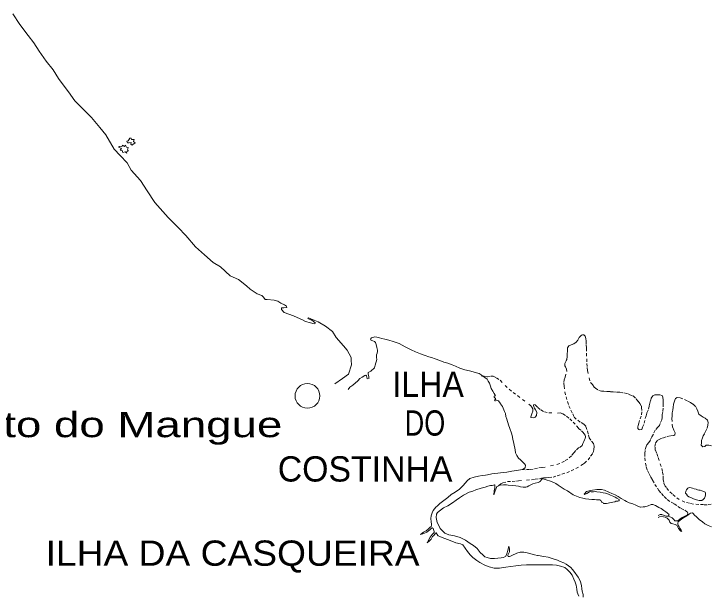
# Model space of a CAD drawing. Extents: x 47169 to 972804, y 7447977 to 9608469.
# Drawn here: x 737887 to 756613, y 9434013 to 9449735 of the extents above; entities that cross this region are included whole.
import ezdxf

# ---------------------------------------------------------------- set-up
doc = ezdxf.new("R2010")
doc.units = 0
doc.header["$LTSCALE"] = 270
doc.linetypes.add('DOTTED', pattern=[1.5, 0.3, -1.2])
doc.layers.add('1', color=7, linetype='Continuous', lineweight=13)
doc.layers.add('2', color=7, linetype='Continuous', lineweight=13)
doc.layers.add('3', color=7, linetype='Continuous')

msp = doc.modelspace()

# ---------------------------------------------------------------- linework, layer by layer
at = {"layer": '1'}
for points in [[(746533.7, 9439762), (746737.2, 9439904), (746899.6, 9440021.8), (746980.3, 9440273.8), (746969.7, 9440401), (746968.8, 9440475.1), (746866.3, 9440668), (746766.9, 9440787.8), (746569.1, 9441015.2), (746472, 9441172.7), (746280.6, 9441317.1), (746079.1, 9441432.9), (745989.3, 9441470.8), (745818.8, 9441541.1), (745805.4, 9441520.1), (745844.1, 9441503.3), (745895.1, 9441485.5), (745936.1, 9441459.9), (746008, 9441394.4), (745979.1, 9441381.2), (745872.6, 9441403.7), (745745.2, 9441441.7), (745661, 9441486.3), (745518.2, 9441552), (745416.2, 9441597.7), (745165.8, 9441680.5), (745094, 9441765.9), (745096.4, 9441806.8), (745155.2, 9441807.7), (745241.7, 9441820.7), (745228.6, 9441858.3), (745172.1, 9441896.1), (745075.7, 9441939.6), (744993.8, 9441987.5), (744901.8, 9442014.3), (744711.1, 9442033.8), (744654.5, 9442034), (744611.5, 9442097.2), (744565, 9442142.7), (744435.4, 9442185.2), (744253.9, 9442311.9), (744151, 9442402.9), (743934.2, 9442577.3), (743717, 9442669.9), (743453.9, 9442918.6), (743254.6, 9443029.9), (743022.3, 9443241.9), (742774.5, 9443457.4), (742518.2, 9443761.3), (742315.9, 9443976.6), (742045, 9444247.4), (741681.4, 9444653.5), (741473.8, 9444967.3), (741299.5, 9445244.4), (741048.6, 9445525.1), (740940.5, 9445717.9), (740745.9, 9445913.3), (740584.5, 9446085.3), (740363.9, 9446471), (740200.4, 9446671.7), (739980.5, 9446945.7), (739527.1, 9447394.1), (739356, 9447636.9), (739214.6, 9447824.3), (739092, 9447995), (738947.5, 9448231.1), (738756.3, 9448456.3), (738568.6, 9448732.4), (738422.8, 9448953), (738273.7, 9449151.5), (738046.2, 9449450.9), (737854.1, 9449734.7)], [(751534.3, 9437441.4), (751588.7, 9437450.1), (751658.7, 9437496.3), (751665.6, 9437570.4), (751644.7, 9437608.1), (751577.2, 9437665.8), (751533, 9437710.2), (751475.5, 9437759.1), (751430.2, 9437827.9), (751396.1, 9437897.7), (751385.3, 9437985.1), (751352.6, 9438151.2), (751328.6, 9438268.5), (751309, 9438368.2), (751290.4, 9438429.1), (751243.1, 9438562), (751206.8, 9438655), (751164.1, 9438813.4), (751137.7, 9438877.6), (751125.8, 9438959.6), (751102.7, 9439013.8), (751048.8, 9439146.8), (750998.1, 9439223.3), (750981.5, 9439242.2), (750939.5, 9439299.8), (750900.7, 9439309.9), (750863, 9439300.1), (750838.6, 9439300.2), (750836.5, 9439331.2), (750856.4, 9439336.6), (750870.9, 9439348.7), (750863.2, 9439368.7), (750841.1, 9439387.6), (750822.3, 9439404.2), (750826.8, 9439427.4), (750856.8, 9439440.6), (750850.2, 9439459.4), (750822.6, 9439502.7), (750786.2, 9439562.6), (750742.1, 9439634.6), (750722.4, 9439697.7), (750699.3, 9439776.4), (750666.3, 9439835.1), (750632.1, 9439887.2), (750572.3, 9439929.5), (750518.1, 9439968.4), (750473.8, 9440000.6), (750415.2, 9440038.4), (750347.6, 9440059.7), (750261.1, 9440082.1), (750160.3, 9440114.5), (750037.2, 9440143.7), (749898.7, 9440185.1), (749783.5, 9440234.2), (749692.7, 9440272.1), (749576.3, 9440317.9), (749472.2, 9440349.2), (749359.2, 9440392.8), (749231.8, 9440436.4), (749134.2, 9440467.7), (749064.4, 9440493.4), (748961.4, 9440529.1), (748837.3, 9440574.9), (748705.5, 9440622.9), (748586.9, 9440677.5), (748495, 9440725.4), (748427.5, 9440757.7), (748345.5, 9440803.4), (748266.9, 9440847.9), (748181.6, 9440880.3), (748100.7, 9440903.8), (747989.9, 9440935.1), (747876.8, 9440967.6), (747795.9, 9440986.7), (747736.1, 9441004.6), (747664, 9441015.9), (747608.6, 9441028.3), (747520.9, 9441003.1), (747490.8, 9440965.6), (747511.8, 9440933.5), (747558.3, 9440921.1), (747596, 9440903.3), (747626.9, 9440875.6), (747648.9, 9440818), (747660.9, 9440743.8), (747678.4, 9440674), (747679.3, 9440633.1), (747670.3, 9440584.5), (747655.7, 9440540.2), (747656.7, 9440503.7), (747655.5, 9440467.2), (747658.7, 9440424.1), (747657.4, 9440382.1), (747640.6, 9440325.7), (747617.1, 9440264.9), (747604.6, 9440195.3), (747503.4, 9440107.1), (747430, 9440069.8), (747429.9, 9440032.2), (747445.1, 9439946.9), (747449.4, 9439897.1)], [(746889.3, 9439611.4), (746938.3, 9439673.2), (747017.3, 9439729.4), (747150.8, 9439842.8), (747204.3, 9439904.6), (747264.3, 9439942), (747343.2, 9439987.1), (747364.3, 9439999.2), (747386.4, 9439978.1), (747406.2, 9439906.1), (747412.8, 9439895.1)], [(748842.2, 9435697.3), (748922.7, 9435762.4), (748990.4, 9435796.4), (749043.9, 9435846), (749091.7, 9435884.6), (749122.9, 9435919.9), (749134.1, 9435950.8), (749135.3, 9435981.8), (749128.8, 9436042.7), (749117, 9436127.9), (749127.2, 9436199.8), (749157.4, 9436288.1), (749177.6, 9436344.5), (749214.4, 9436390.8), (749251.1, 9436433.8), (749296.7, 9436471.3), (749359.1, 9436533), (749433.6, 9436587), (749577.1, 9436700.4), (749669.4, 9436780.9), (749769.5, 9436839.1), (749888.4, 9436920.6), (749984.2, 9437025.3), (750093.3, 9437143.3), (750172.3, 9437208.3), (750285.6, 9437247.8), (750397.8, 9437275), (750503.2, 9437290.2), (750587.5, 9437300.9), (750644.1, 9437308.5), (750762.9, 9437331.3), (750920.5, 9437356.2), (751061.5, 9437374.5), (751168, 9437384.1), (751299, 9437404.6), (751423.3, 9437426.3), (751534.3, 9437441.4)], [(750817.5, 9436769.1), (750826.1, 9436880.3), (750843.7, 9436962.6), (750841.7, 9437026.8), (750828.4, 9437035.7), (750806.2, 9437029.1), (750768.5, 9437024.8), (750726.3, 9437019.4), (750654.2, 9437000.9), (750580.8, 9436972.4), (750474.2, 9436946.2), (750333.2, 9436903.6), (750246.6, 9436869.6), (750154.4, 9436840), (749999.9, 9436764.2), (749893.2, 9436689.4), (749804.2, 9436628.8), (749698.6, 9436555.1), (749571.8, 9436469.2), (749455.2, 9436422.1), (749374, 9436359.3), (749300.6, 9436297.6), (749270.4, 9436245.7), (749264.6, 9436156.1), (749285.2, 9436026.6), (749321.6, 9435956.8), (749367.8, 9435863.7), (749439.7, 9435791.6), (749496.1, 9435738.3), (749603.5, 9435694.7), (749755.4, 9435664.3), (749910.5, 9435621.8), (750048.9, 9435550.5), (750174, 9435458.2), (750262.5, 9435402.6), (750364.3, 9435319.3), (750442.7, 9435212.8), (750515.7, 9435152.8), (750573.2, 9435099.5), (750637.4, 9435078.2), (750727.2, 9435056.9), (750835.9, 9435053.2), (751010.1, 9435069.2), (751075.6, 9435084.5), (751135.6, 9435114.1), (751166.9, 9435179.3), (751192.7, 9435265.5), (751218.1, 9435387.4)], [(754734.5, 9436445.5), (754713.4, 9436451.1), (754639.2, 9436487.9), (754555.1, 9436528), (754464.2, 9436558.2), (754391.1, 9436588.3), (754339, 9436612.8), (754241.6, 9436668.5), (754166.4, 9436720.8), (754085.6, 9436768.6), (753993.6, 9436807.7), (753910.6, 9436845.6), (753797.6, 9436896.9), (753712.2, 9436916), (753589.1, 9436915.3), (753474.8, 9436898), (753386, 9436880.6), (753311.6, 9436859.9), (753252.6, 9436800.3), (753248.1, 9436784.9), (753255.8, 9436781.5), (753319.1, 9436806.8), (753392.5, 9436847.4), (753417, 9436856.2), (753435.8, 9436847.3), (753468, 9436847.2), (753501.2, 9436853.7), (753541.2, 9436863.5), (753591.1, 9436850), (753683.1, 9436838.7), (753757.4, 9436827.3), (753822.8, 9436811.6), (753907, 9436783.7), (753955.7, 9436762.5), (754048.8, 9436726.7), (754086.4, 9436703.4), (754129.6, 9436675.6), (754190.5, 9436639.9), (754190.4, 9436616.7), (754177.1, 9436607.9), (754156, 9436596.9), (754104.9, 9436596), (754078.2, 9436581.7), (754020.5, 9436573), (753978.3, 9436565.5), (753852.9, 9436539.3), (753785.2, 9436539.6), (753767.5, 9436539.7), (753755.3, 9436549.7), (753722.1, 9436568.6), (753711, 9436580.8), (753699, 9436612.9), (753673.5, 9436632.9), (753655.8, 9436633), (753615.8, 9436636.4), (753583.7, 9436637.7), (753527.1, 9436645.6), (753451.7, 9436648.1), (753374.1, 9436656.1), (753286.5, 9436663.1), (753215.5, 9436675.5), (753126.9, 9436701.2), (753041.6, 9436736.9), (752953, 9436773.8), (752802.5, 9436879.4), (752707.2, 9436924), (752630.9, 9436978.5), (752551.2, 9437028.5), (752483.7, 9437077.4), (752387.3, 9437124.2), (752316.4, 9437149.9), (752247.7, 9437162.3), (752198.9, 9437180.2), (752142.4, 9437200.3), (752114.7, 9437200.4), (752100.2, 9437187.2), (752082.4, 9437155.2), (752075.7, 9437140.8), (752042.3, 9437122.1), (752004.6, 9437105.7), (751924.6, 9437082.7), (751869.1, 9437066.3), (751796.8, 9437034.5), (751754.6, 9437012.5), (751713.5, 9436989.4), (751672.4, 9436976.3), (751607, 9436976.5), (751534.9, 9436987.8), (751477.2, 9436999.1), (751404.1, 9437010.4), (751314.3, 9437021.8), (751201.1, 9437032.2), (751155.7, 9437036.7), (751071.4, 9437039.2), (750982.6, 9437030.7), (750940.4, 9437015.4), (750903.7, 9436994.5), (750898.2, 9436990.1), (750885.9, 9436971.3), (750848.9, 9436875.2), (750817.5, 9436769.1)], [(755237.3, 9436208.1), (755258.4, 9436220.2), (755296.2, 9436237.7), (755343.8, 9436235.3), (755399.2, 9436214.1), (755453.5, 9436195.1), (755506.8, 9436191.6), (755541.3, 9436228), (755524.7, 9436248), (755497.1, 9436269.1), (755479.4, 9436286.8), (755444, 9436309.1), (755390.8, 9436349.1), (755323.4, 9436402.5), (755260.2, 9436431.5), (755170.6, 9436486), (755096.3, 9436509.5), (755054.2, 9436509.6), (754969.8, 9436476.8), (754883.1, 9436449.4), (754833.2, 9436442.9), (754767.7, 9436439.8), (754757.8, 9436439.9), (754734.5, 9436445.5)], [(756676.1, 9435904.2), (756589.7, 9435944.3), (756498.9, 9435987.8), (756433.6, 9436042.2), (756347.3, 9436109), (756274.4, 9436175.6), (756215.8, 9436224.5), (756184.8, 9436262.2), (756162.7, 9436283.3), (756115, 9436277.9), (756082.7, 9436253.7), (756012.7, 9436207.5), (755903.7, 9436138.2), (755837, 9436089.8), (755780.2, 9436039.1), (755770.1, 9436007), (755773.3, 9435977.1), (755784.3, 9435938.4), (755803.1, 9435907.3), (755821.8, 9435868.6), (755860.4, 9435816.4), (755880.3, 9435785.4), (755852.6, 9435789.9), (755822.7, 9435813.2), (755809.5, 9435842), (755791.8, 9435866.5), (755752.1, 9435934.1), (755745.5, 9435951.8), (755736.7, 9435955.2), (755700.1, 9435973), (755638.1, 9435987.6), (755593.7, 9435995.5), (755559.5, 9436034.3), (755545.1, 9436060.9), (755534.1, 9436087.5), (755481.1, 9436143), (755425.7, 9436168.7), (755381.4, 9436174.4), (755318.2, 9436190.1), (755272.7, 9436177), (755241.5, 9436159.4)], [(749018.8, 9435476), (749100.8, 9435625.7), (749153.2, 9435703), (749208.8, 9435757), (749206.7, 9435785.7), (749184.8, 9435859.9), (749153.8, 9435883.3), (749137.1, 9435873.4), (749114.9, 9435855.8), (749091.5, 9435828.2), (749057, 9435798.4), (749013.6, 9435766.5), (748929.2, 9435729.2), (748842.2, 9435697.3)], [(753103, 9434037.4), (753078.8, 9434100.5), (753063.5, 9434149.2), (753048.2, 9434229), (753030.8, 9434336.3), (753001.2, 9434411.7), (752973.7, 9434494.7), (752923.1, 9434607.8), (752857.9, 9434687.6), (752788.3, 9434756.5), (752726.4, 9434809.8), (752612.2, 9434847.8), (752499.2, 9434870.3), (752398.3, 9434886.2), (752152, 9434885.9), (752050, 9434886.3), (751881.4, 9434885.8), (751696.1, 9434884.2), (751554.1, 9434878.1), (751407.6, 9434856.5), (751133.5, 9434818.7), (750971.4, 9434791.7), (750820.6, 9434793.3), (750690.9, 9434828), (750569, 9434873.8), (750438.4, 9434945.1), (750357.6, 9435000.7), (750252.5, 9435080.7), (750180.7, 9435149.6), (750108.9, 9435241.6), (749975.3, 9435421.3), (749913.3, 9435451.4), (749791.3, 9435479.5), (749596.4, 9435558.7), (749467.8, 9435600.1), (749363.7, 9435642.5), (749315, 9435662.6), (749313.9, 9435662.6), (749306.2, 9435673.7), (749259.8, 9435742.4), (749246.5, 9435740.2), (749227.5, 9435709.3), (749201.9, 9435677.3), (749164.1, 9435647.6), (749122.8, 9435575.8), (749085, 9435530.5), (749018.8, 9435476)], [(751218.1, 9435387.4), (751237.9, 9435308.7), (751232.6, 9435230), (751222.4, 9435193.5), (751195.6, 9435143.8), (751194.4, 9435122.8), (751202.2, 9435109.4), (751233.2, 9435110.4), (751259.8, 9435113.7), (751299.8, 9435130.1), (751435.4, 9435201.6), (751519.8, 9435226.7), (751619.7, 9435225.2), (751716.1, 9435206.1), (751913.3, 9435150.1), (751989.8, 9435136.5), (752004.3, 9435134.3), (752163.9, 9435107.2), (752274.8, 9435085.8), (752357.9, 9435063.3), (752441, 9435039.8), (752532.9, 9435005.2), (752603.8, 9434970.6), (752696.8, 9434932.7), (752765.5, 9434902.6), (752823, 9434855.9), (752885, 9434811.4), (752929.2, 9434760.4), (752966.7, 9434709.4), (753082.6, 9434553), (753124.6, 9434487.6), (753147.6, 9434424.4), (753173.9, 9434327), (753181.4, 9434238.4), (753192.2, 9434168.7), (753220.7, 9434081.2), (753222.7, 9434012.6)]]:
    msp.add_lwpolyline(points, dxfattribs=at)
for points in [[(741042.2, 9446264.1), (740994.4, 9446258.7), (740949, 9446255.5), (740932.5, 9446304.2), (740961.3, 9446309.7), (740983.6, 9446337.3), (741006, 9446383.6), (741044.8, 9446381.3), (741058, 9446348.1), (741083.5, 9446345.8), (741126.8, 9446345.6), (741111.1, 9446294.8), (741152, 9446261.5), (741116.4, 9446236.2), (741104.2, 9446220.7), (741073, 9446197.6), (741035.4, 9446220.9)], [(740734.5, 9446155.6), (740795.5, 9446155.3), (740811.2, 9446194), (740864.3, 9446164), (740895.5, 9446197.1), (740918.6, 9446138.4), (740961.9, 9446136), (740947.2, 9446059.7), (740974.9, 9446047.5), (740923.8, 9446018.9), (740929.2, 9445983.5), (740882.7, 9446015.7), (740817.2, 9445994.9), (740804.1, 9446049.1), (740745.3, 9446063.7), (740788.7, 9446102.3), (740702.3, 9446142.4)], [(756484.8, 9436682.6), (756456.9, 9436646.2), (756415.8, 9436620.9), (756344.7, 9436616.8), (756273.8, 9436636.9), (756192.9, 9436661.6), (756117.6, 9436696.1), (756066.6, 9436716.2), (756033.5, 9436746.2), (756000.3, 9436785), (755981.6, 9436816.1), (755986.2, 9436865.8), (756008.5, 9436906.7), (756039.7, 9436946.4), (756079.7, 9436962.9), (756128.5, 9436961.6), (756165.1, 9436950.4), (756213.9, 9436934.7), (756263.7, 9436919.1), (756301.4, 9436900.1), (756335.8, 9436896.7), (756372.3, 9436894.3), (756421.1, 9436879.8), (756473.2, 9436861.9), (756506.4, 9436837.4), (756515.2, 9436810.8), (756515, 9436772.1), (756507.1, 9436722.4)]]:
    msp.add_lwpolyline(points, close=True, dxfattribs=at)
at = {"layer": '1', "linetype": 'DOTTED'}
for points in [[(750940.4, 9437015.4), (750951.5, 9437023.1), (751000.5, 9437067.2), (751054.9, 9437093.5), (751179.3, 9437125.2), (751312.4, 9437132.4), (751426.7, 9437134.2), (751482.2, 9437146.2), (751690.8, 9437162.1), (751831.8, 9437176), (751929.4, 9437188.9), (752040.4, 9437204), (752102.6, 9437221.5), (752152.5, 9437225.7), (752223.5, 9437226.6), (752300.1, 9437234.1), (752408.8, 9437248.1), (752522.1, 9437280.8), (752649.8, 9437330.2), (752782, 9437364), (752898.7, 9437421.1), (753023.1, 9437476), (753156.5, 9437557.4), (753204.3, 9437590.4), (753258.8, 9437619), (753351.2, 9437714.9), (753422.5, 9437809.8), (753472.7, 9437883.7), (753495.1, 9437935.7), (753509.7, 9437988.7), (753517.8, 9438077.2), (753495.9, 9438154.7), (753427.4, 9438243.4), (753385.5, 9438307.8), (753354.8, 9438413), (753321.9, 9438532.6), (753290.1, 9438620.1), (753237, 9438674.5), (753139.6, 9438732.3), (753035.6, 9438805.7), (752967, 9438877.9), (752927.5, 9438984.2), (752869.1, 9439097.2), (752821.8, 9439209.1), (752781.2, 9439337.6), (752745, 9439466.1), (752716.8, 9439629.9), (752711.5, 9439702.9), (752701.8, 9439794.8), (752707.6, 9439873.3), (752733.4, 9439944), (752780.5, 9440098.8), (752776.3, 9440153), (752744.4, 9440223.9), (752728.9, 9440250.5), (752726.9, 9440309.1), (752762.7, 9440389.8), (752782.8, 9440419.6), (752788.6, 9440501.4), (752793.3, 9440579.9), (752796.8, 9440636.3), (752794.8, 9440688.3), (752802.7, 9440734.8), (752832.9, 9440787.8), (752901.8, 9440817.4), (752968.4, 9440836), (753035.1, 9440885.5), (753080.8, 9440941.8), (753111, 9441007), (753146.6, 9441046.7), (753172.2, 9441069.8), (753198.9, 9441080.8), (753239.9, 9441081.7), (753277.5, 9441045.1), (753293.9, 9440984.2), (753300.3, 9440908.9), (753305.6, 9440817.1), (753306.3, 9440719.7), (753310.3, 9440587), (753316.4, 9440438.7), (753321.5, 9440312.6), (753331.1, 9440200.8), (753339.7, 9440123.3), (753379, 9439923), (753418.5, 9439796.7), (753472.6, 9439742.3), (753519, 9439671.3), (753548.8, 9439646.9), (753645.1, 9439583.5), (753718.3, 9439563.3), (753774.8, 9439562), (753866.9, 9439558.4), (753956.7, 9439550.3), (754031.1, 9439544.5), (754126.4, 9439534.2), (754209.6, 9439533.9), (754320.5, 9439519.2), (754414.7, 9439500), (754477.9, 9439468.8), (754566.5, 9439434.2), (754648.3, 9439358.7)], [(750473.8, 9440000.6), (750489.2, 9439970.7), (750555.8, 9439966), (750647.8, 9439951.3), (750743.3, 9439967.6), (750796.5, 9439967.4), (750885.1, 9439923.9), (750983.6, 9439860.6), (751117.4, 9439720.7), (751226.8, 9439618.5), (751335.2, 9439526.3), (751450.3, 9439445.2), (751585.3, 9439344), (751756.8, 9439214), (751808.8, 9439171.8), (751841.9, 9439132.9), (751866.2, 9439091.9), (751861.5, 9439023.3), (751838, 9438951.5), (751813.3, 9438872), (751809.9, 9438850.9), (751872, 9438846.3), (751928.6, 9438867.1), (751963.2, 9438909), (751969.1, 9438999.7), (751940.4, 9439060.7), (751911.7, 9439103.9), (751893, 9439140.5), (751879.9, 9439190.3), (751891, 9439202.5), (751932, 9439192.4), (751999.4, 9439123.5), (752076.9, 9439059.1), (752175.4, 9439005.7), (752296.2, 9438980.9), (752533.6, 9438975.6), (752599.1, 9438976.5), (752674.4, 9438956.3), (752773, 9438892.9), (752858.1, 9438817.4), (752948.8, 9438728.6), (753042.7, 9438630.9), (753099.1, 9438562.1), (753176.5, 9438498.8), (753213, 9438461), (753247.2, 9438417.8), (753277, 9438375.6), (753286.8, 9438329.1), (753277.8, 9438287.1), (753254.4, 9438251.8), (753243.1, 9438205.4), (753208.5, 9438154.6), (753193.9, 9438099.3), (753136.1, 9438050.9), (753099.4, 9438037.7), (753027, 9437961.6), (752968, 9437901), (752904.5, 9437823.8), (752806.6, 9437735.6), (752716.5, 9437679.5), (752593.2, 9437612.5), (752423.3, 9437565.5), (752193.5, 9437516.5), (752104.7, 9437506.9), (751988.1, 9437487.4), (751874.9, 9437464.6), (751773.9, 9437452.7), (751660.8, 9437446.5), (751588.7, 9437450.1)], [(754648.3, 9439358.7), (754700.2, 9439291), (754743.3, 9439234.5), (754788.5, 9439163.5), (754796.1, 9439120.3), (754800.2, 9439004.1), (754783.1, 9438892.5), (754740.5, 9438770.9), (754721.4, 9438702.4), (754701.2, 9438636.1), (754694.4, 9438599.6), (754693.2, 9438559.8), (754717.5, 9438527.6), (754747.4, 9438522), (754797.4, 9438534), (754823.1, 9438591.4), (754864.5, 9438697.5), (754894.9, 9438826.8), (754914, 9438895.3), (754939.8, 9438977.1), (754984.6, 9439083.1), (754998.2, 9439172.7), (755015.1, 9439237.9), (755040.9, 9439325.2), (755053.3, 9439372.7), (755094.6, 9439437.9), (755149, 9439468.6), (755181.2, 9439468.5), (755236.6, 9439461.7), (755283.3, 9439467.1), (755347.5, 9439443.6), (755370.7, 9439403.7), (755372.6, 9439314.1), (755374.5, 9439222.2), (755372.9, 9439106.1), (755362.6, 9439005.5), (755352.3, 9438931.4), (755346.5, 9438852.8), (755337.4, 9438792), (755297.2, 9438695.9), (755272.6, 9438639.6), (755230.2, 9438593.3), (755160.1, 9438516.1), (755110.9, 9438408.9), (755071.8, 9438330.5), (755031.5, 9438247.7), (754990.2, 9438178.2), (754940.1, 9438118.6), (754913.3, 9438068.9), (754886.3, 9437961.7), (754880.5, 9437883.2), (754885.6, 9437768.1), (754898.4, 9437623.1), (754920.2, 9437524.6), (754953.2, 9437427.1), (754997.2, 9437336.2), (755012.6, 9437303), (755044.6, 9437242), (755092, 9437161.1), (755152.6, 9437048.1), (755219.9, 9436949.3), (755263, 9436887.2), (755331.5, 9436802.9), (755406.6, 9436723), (755487.3, 9436639.7), (755589.1, 9436570.8), (755675.5, 9436529.5), (755771.7, 9436459.5), (755863.6, 9436397.2), (755955.5, 9436352.6), (756002, 9436321.5), (756031.9, 9436300.4), (756044, 9436282.6), (756030.5, 9436230.7), (755955, 9436197.8), (755883.8, 9436156), (755827.1, 9436113), (755772.6, 9436072.3), (755768.1, 9436065.7), (755692.7, 9436071.5), (755662.9, 9436107), (755616.5, 9436151.4), (755583.2, 9436163.7), (755552.2, 9436173.8), (755506.8, 9436191.6)], [(756668.3, 9436518.2), (756562.9, 9436504.2), (756458.6, 9436504.6), (756335.5, 9436507.3), (756189.1, 9436518.8), (756082.7, 9436546.9), (755959.6, 9436576.1), (755809, 9436644.1), (755700.6, 9436726.4), (755617.7, 9436799.7), (755520.3, 9436883), (755461.8, 9436964), (755428.7, 9437006.1), (755389.1, 9437100.3), (755376.1, 9437195.5), (755372.1, 9437301.7), (755359.1, 9437402.4), (755320.7, 9437530.9), (755263.7, 9437698.2), (755234.1, 9437804.5), (755200, 9437897.5), (755163.7, 9437974), (755155.2, 9438070.3), (755172.2, 9438170.9), (755229, 9438247), (755306.8, 9438286.6), (755383.4, 9438308.4), (755484.5, 9438342.3), (755581.1, 9438363), (755665.4, 9438371.6), (755692.1, 9438391.4), (755701.2, 9438442.2), (755667, 9438512.1), (755629.6, 9438593), (755614.6, 9438743.5), (755612.7, 9438823.1), (755615.1, 9438892.8), (755619.9, 9438978), (755632.3, 9439054.3), (755641.5, 9439129.5), (755658.4, 9439213.5), (755676.5, 9439290.9), (755698.8, 9439347.2), (755708.9, 9439363.8), (755751.1, 9439389.1), (755832.1, 9439385.5), (755946.2, 9439337.5), (756035.9, 9439294), (756109, 9439258.3), (756187.6, 9439209.4), (756251.7, 9439146.1), (756284.8, 9439091.8), (756310.1, 9439028.6), (756323.2, 9438967.7), (756335.3, 9438944.5), (756398.4, 9438901.1), (756449.3, 9438864.4), (756509.1, 9438833.2), (756572.1, 9438778.8), (756585.2, 9438721.2), (756580.5, 9438644.9), (756553.6, 9438552.1), (756521.2, 9438493.5), (756485.4, 9438418.4), (756457.5, 9438364.3), (756434, 9438305.8), (756410.4, 9438232.8), (756404.6, 9438169.8), (756402.2, 9438106.8), (756444.2, 9438061.2), (756497.5, 9438072.1), (756536.4, 9438104.1), (756605.2, 9438110.5), (756675, 9438090.3)]]:
    msp.add_lwpolyline(points, dxfattribs=at)
at = {"layer": '2'}
msp.add_circle((745793.8, 9439437.1), 333.1, dxfattribs=at)

# ---------------------------------------------------------------- texts
at = {"layer": '3'}
for s, height, width, p in [('ILHA', 680.9, 0.95, (748083.6, 9439409.1)), ('Canto do Mangue', 680.8, 1.35, (735346.1, 9438323.9)), ('DO', 680.9, 0.8, (748413.1, 9438366.2)), ('ILHA DA CASQUEIRA', 680.8, 1.1, (738742.3, 9434857.6))]:
    msp.add_text(s, height=height, dxfattribs=dict(at, width=width)).set_placement(p)
msp.add_text('COSTINHA', height=680.9, dxfattribs=at).set_placement((744994.8, 9437128))

doc.saveas('drawing.dxf')
